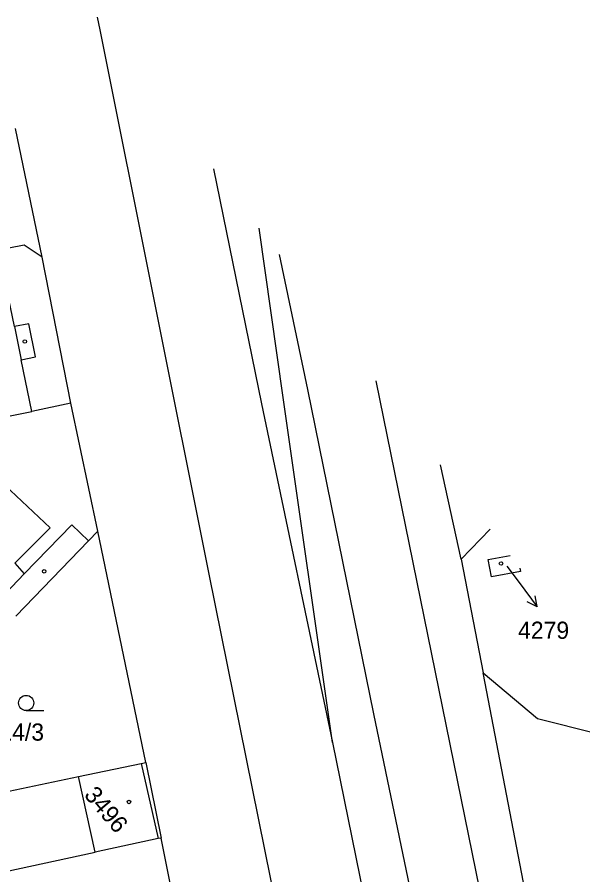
# Model space of a CAD drawing. Extents: x -679220 to -673243, y -1075091 to -1066557.
# Drawn here: x -675798.9 to -675742.9, y -1071743.1 to -1071658.2 of the extents above; entities that cross this region are included whole.
import ezdxf

# ---------------------------------------------------------------- set-up
doc = ezdxf.new("R2010")
doc.units = 0
for name, color, linetype in [('Hranice parcel', 7, 'Continuous'), ('Parcelní čísla', 7, 'Continuous'), ('Pop  PČ popisy', 7, 'Continuous'), ('Poz předměty', 7, 'Continuous'), ('Vnitřní kresba', 7, 'Continuous'), ('Značky budov', 7, 'Continuous'), ('Značky kultur', 7, 'Continuous')]:
    doc.layers.add(name, color=color, linetype=linetype)

msp = doc.modelspace()

# ---------------------------------------------------------------- linework, layer by layer
at = {"layer": 'Hranice parcel'}
for p, q in [((-675796.44, -1071681.97), (-675799.09, -1071669.23)), ((-675793.62, -1071696.4), (-675796.44, -1071681.97)), ((-675790.93, -1071709.09), (-675793.62, -1071696.4)), ((-675754.98, -1071711.84), (-675757.007, -1071702.511)), ((-675786.2, -1071731.99), (-675790.93, -1071709.09)), ((-675752.111, -1071708.892), (-675754.98, -1071711.84)), ((-675754.98, -1071711.84), (-675752.81, -1071723.11)), ((-675786.2, -1071731.99), (-675784.68, -1071739.46)), ((-675791.2, -1071740.86), (-675792.86, -1071733.38)), ((-675783, -1071747.74), (-675784.68, -1071739.46))]:
    msp.add_line(p, q, dxfattribs=at)
for points in [[(-675791.003, -1071658.205), (-675790.75, -1071659.46), (-675779.94, -1071713.34), (-675771.38, -1071755.76), (-675762.14, -1071796.42), (-675752.49, -1071841.88)], [(-675796.44, -1071681.97), (-675798.24, -1071680.76), (-675823.18, -1071685.65), (-675827.92, -1071690.76)], [(-675793.62, -1071696.4), (-675797.49, -1071697.24), (-675798.53, -1071692.12), (-675797.11, -1071691.83), (-675797.78, -1071688.55), (-675799.2, -1071688.84), (-675799.95, -1071685.16), (-675810.38, -1071687.29), (-675810.92, -1071687.45), (-675811.29, -1071687.97), (-675810.91, -1071689.69), (-675810.4, -1071690.01), (-675809.84, -1071689.89), (-675807.89, -1071699.36), (-675803.38, -1071698.44), (-675803.02, -1071700.21), (-675802.88, -1071700.18), (-675802.42, -1071702.43), (-675795.65, -1071708.76), (-675799.17, -1071712.26), (-675798.23, -1071713.32), (-675800.74, -1071715.91)], [(-675734.17, -1071838.14), (-675745.07, -1071784.11), (-675763.395, -1071694.187)], [(-675799.07, -1071717.5), (-675791.87, -1071710.05), (-675790.93, -1071709.09)], [(-675751.97, -1071713.61), (-675752.3, -1071711.9), (-675750.128, -1071711.476)], [(-675749.154, -1071712.747), (-675749.09, -1071713.07), (-675751.97, -1071713.61)], [(-675732.57, -1071825.94), (-675741.19, -1071783.47), (-675752.81, -1071723.11)], [(-675752.81, -1071723.11), (-675747.42, -1071727.63), (-675741.52, -1071729.12), (-675735.89, -1071756.51), (-675726.24, -1071802.79), (-675721.83, -1071824.51)], [(-675812.49, -1071731.35), (-675807.31, -1071736.39), (-675792.86, -1071733.38)], [(-675792.86, -1071733.38), (-675786.64, -1071732.08), (-675786.2, -1071731.99)], [(-675784.68, -1071739.46), (-675784.97, -1071739.52), (-675791.2, -1071740.86)], [(-675810.37, -1071745.94), (-675809.26, -1071744.74), (-675791.2, -1071740.86)]]:
    msp.add_lwpolyline(points, dxfattribs=at)
at = {"layer": 'Pop  PČ popisy'}
for p, q in [((-675750.47, -1071712.55), (-675749.25, -1071714.18)), ((-675749.25, -1071714.18), (-675747.444, -1071716.577)), ((-675747.444, -1071716.577), (-675747.647, -1071715.476)), ((-675747.444, -1071716.577), (-675748.447, -1071716.078))]:
    msp.add_line(p, q, dxfattribs=at)
at = {"layer": 'Poz předměty'}
for p, q in [((-675779.494, -1071673.204), (-675774.75, -1071696.47)), ((-675772.6, -1071695.85), (-675774.984, -1071679.082)), ((-675772.987, -1071681.684), (-675770.2, -1071695.05)), ((-675770.2, -1071695.05), (-675763.65, -1071727.18)), ((-675767.7, -1071730.01), (-675772.6, -1071695.85)), ((-675774.75, -1071696.47), (-675767.7, -1071730.01)), ((-675763.65, -1071727.18), (-675757.39, -1071757.34)), ((-675767.7, -1071730.01), (-675762.17, -1071757.3))]:
    msp.add_line(p, q, dxfattribs=at)
at = {"layer": 'Vnitřní kresba'}
for p, q in [((-675799.2, -1071688.84), (-675798.53, -1071692.12)), ((-675799.78, -1071697.71), (-675797.49, -1071697.24)), ((-675793.52, -1071708.45), (-675798.23, -1071713.32)), ((-675791.87, -1071710.05), (-675793.52, -1071708.45)), ((-675786.64, -1071732.08), (-675784.97, -1071739.52))]:
    msp.add_line(p, q, dxfattribs=at)
at = {"layer": 'Značky budov'}
for centre in [(-675798.167, -1071690.309), (-675751.027, -1071712.279), (-675796.257, -1071713.059), (-675787.857, -1071735.889)]:
    msp.add_circle(centre, 0.175, dxfattribs=at)
at = {"layer": 'Značky kultur'}
msp.add_line((-675798.043, -1071726.84), (-675796.293, -1071726.84), dxfattribs=at)
msp.add_circle((-675798.043, -1071726.09), 0.75, dxfattribs=at)

# ---------------------------------------------------------------- texts
at = {"layer": 'Parcelní čísla'}
for s, p in [('4279', (-675749.344, -1071719.739)), ('514/3', (-675801.958, -1071729.82))]:
    msp.add_text(s, height=1.7, dxfattribs=at).set_placement(p)
msp.add_text('3496', height=1.7, rotation=310, dxfattribs=at).set_placement((-675792.382, -1071735.237))

doc.saveas('drawing.dxf')
